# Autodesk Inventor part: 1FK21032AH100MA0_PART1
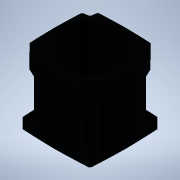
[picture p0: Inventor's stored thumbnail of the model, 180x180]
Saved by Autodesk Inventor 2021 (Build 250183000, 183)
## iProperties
Created: 2025-04
Part Number: 1FK21032AH100MA0_PART1
Material: Generic
Catalog Web Link: www.3dfindit.com
Description: -Servo synchronous motor
Document SubType Name: Modeling
Designer: psAdmin
Mass: 67.0011 g
Surface Area: 303.908 cm^2
Volume: 67.0011 cm^3
Density: 1 g/cm^3
Appearance: PSOLRGB-176-176-176
Category: PARTsolutions
Title: 1FK21032AH100MA0_PART1
Author: Cadenas PARTsolutions
Comments: Servo synchronous motor
Sending System: PARTsolutions
Preprocessor: ST-DEVELOPER v19.3
PSOL_IDENT_0: {$CADENAS_DATA/23d-libs/siemens_ag/_cat_/12/33/1fk21032ah100ma0.prj},213 {VTYP=3D},{NB=1FK21032AH100
PSOL_IDENT_1: MA0_PART1},{LINA=1FK21032AH100MA0_PART1},{NN=1FK21032AH100MA0_PART1},{NOPRJ=TRUE},{DATE=19.08.2025 1
PSOL_IDENT_2: 4:00:27},{GEOMDATE=30.07.2025 02:02:58},{VERSION=},{LINEID=10},{WBVAR=},{WBNUMERIC=}  {NB=1FK21032AH
PSOL_IDENT_3: 100MA0_PART1},{LINA=1FK21032AH100MA0_PART1},{KT=DUMMY},{PREVIEW=../../../_pool_/d3/78/p_d211_xx_0093
PSOL_IDENT_4: 4j.png},{DESCSHORT=SIMOTICS S-1FK2 HD, SINAMICS S210 3AC 400V-480V, 0.59 Nm, 4500 rpm},{DESCLONG=SIM
PSOL_IDENT_5: OTICS S-1FK2 HD servo motor M0=0.64 Nm; PN = 0.28 kW at nN=4500 rpm (380-480 V); PN = 0.167 kW at nN=
PSOL_IDENT_6: 2500 rpm (200-240 V); with holding brake; degree of protection IP64; cylindrical shaft D14 x 30 mm;
PSOL_IDENT_7: absolute encoder 22-bit + 12-bit multiturn (encoder AM22DQC); with OCC interface; plug size M17, rot
PSOL_IDENT_8: atable; SIMOTICS S-1FK2 servomotorfor a wide range of uses in industrial environments. SIMOTICS S‑1F
PSOL_IDENT_9: K2 servomotors are compact synchronous motors with a high dynamic performance that set themselves ap
PSOL_IDENT_10: art as a result of their high power density, degree of protection and overload capability. The motor
PSOL_IDENT_11: s are available in two variants: as High Dynamic variant (highest dynamic performance as a result of
PSOL_IDENT_12: the low intrinsic moment of inertia for applications demanding a high dynamic performance with low
PSOL_IDENT_13: moved masses) - and as Compact variant (precise and stable closed-loop control for medium up to larg
PSOL_IDENT_14: e moved masses as a result of a medium intrinsic moment of inertia). SIMOTICSS‑1FK2 servomotors full
PSOL_IDENT_15: y exploit their strengths in a system with the SINAMICSS210 frequency converter and simple connectio
PSOL_IDENT_16: n using the one cable connection (OCC). Advantages include the short control and positioning times,
PSOL_IDENT_17: fast and precise correction of disturbing quantities as well as stable control with a high dynamic p
PSOL_IDENT_18: erformance. The servo motors can be configured to address a wide range of requirements. For example
PSOL_IDENT_19: with and without holding brake, IP64 or IP65 degree of protection, singleturn or multiturn absolute
PSOL_IDENT_20: encoders - to name just a few. Further, the servomotors are available in different shaft heights ext
PSOL_IDENT_21: ending from 20 to 100. A shaft sealing ring is available to achieve an IP65 degree of protection and
PSOL_IDENT_22: for subsequent mounting at the motor or as spare part. SIMOTICS - the optimum motor for each and ev
PSOL_IDENT_23: ery motion control application.},{INTNO=195125315563},{SUPPLIERALTNO=1FK2103-2AH10-0MA0},{MANUID=1FK
PSOL_IDENT_24: 21032AH100MA0},{MANUNAME=Siemens},{MANUTYPEDESC=SYNCHRONOUS MOTOR 1FK2 HD 0,64 NM},{AAU732=SIMOTICS}
PSOL_IDENT_25: ,{AAO057=S-1FK2},{AAU734=SIMOTICS S-1FK2 HD servo motor M0=0.64 Nm; PN = 0.28 kW at nN=4500 rpm (380
PSOL_IDENT_26: -480 V); PN = 0.167 kW at nN=2500 rpm (200-240 V); with holding brake; degree of protection IP64; cy
PSOL_IDENT_27: lindrical shaft D14 x 30 mm; absolute encoder 22-bit + 12-bit multiturn (encoder AM22DQC); with OCC
PSOL_IDENT_28: interface; plug size M17, rotatable;},{AAW338=SYNCHRONOUS MOTOR 1FK2 HD 0,64 NM},{AAO742=SIMOTICS},{
PSOL_IDENT_29: AAO663=4034106444723},{NOCUPEROU=1},{PRICEQUANTITY=1},{QUANTITYMIN=1},{QUANTITYINT=1},{CTN=85015100}
PSOL_IDENT_30: ,{COO=RO},{AAO676=1FK2103-2AH10-0MA0},{AAO677=Siemens AG},{ORDERUNIT=C62},{CONTENTUNIT=C62}
NB: 1FK21032AH100MA0_PART1
NT: Servo synchronous motor
NBSYN: $MANUID._PART1
LINA: 1FK21032AH100MA0_PART1
CATALOG: SIEMENS
PREVIEW: ../../../_pool_/d3/78/p_d211_xx_00934j.png
DESCSHORT: SIMOTICS S-1FK2 HD, SINAMICS S210 3AC 400V-480V, 0.59 Nm, 4500 rpm
DESCLONG: SIMOTICS S-1FK2 HD servo motor M0=0.64 Nm; PN = 0.28 kW at nN=4500 rpm (380-480 V); PN = 0.167 kW at nN=2500 rpm (200-240 V); with holding brake; degree of prot
INTNO: 195125315563
SUPPLIERALTNO: 1FK2103-2AH10-0MA0
MANUID: 1FK21032AH100MA0
MANUNAME: Siemens
MANUTYPEDESC: SYNCHRONOUS MOTOR 1FK2 HD 0,64 NM
AAU732: SIMOTICS
AAO057: S-1FK2
AAU734: SIMOTICS S-1FK2 HD servo motor M0=0.64 Nm; PN = 0.28 kW at nN=4500 rpm (380-480 V); PN = 0.167 kW at nN=2500 rpm (200-240 V); with holding brake; degree of prot
AAW338: SYNCHRONOUS MOTOR 1FK2 HD 0,64 NM
AAO742: SIMOTICS
AAO663: 4034106444723.0
NOCUPEROU: 1
PRICEQUANTITY: 1
QUANTITYMIN: 1
QUANTITYINT: 1
CTN: 85015100
COO: RO
ARTICLENO: 1FK21032AH100MA0_PART1
BOMINFO: 1FK21032AH100MA0_PART1
CREATOR: CADENAS GmbH
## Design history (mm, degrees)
feature "2025_04_17_15_06_16_0549"
node "ECLASS_CAX_IMPORTER_001_CP_0_XY"
node "ECLASS_CAX_IMPORTER_001_CP_0_YZ"
node "ECLASS_CAX_IMPORTER_001_CP_0_ZX"
node "ECLASS_CAX_IMPORTER_001_CP_0_X"
node "ECLASS_CAX_IMPORTER_001_CP_0_Y"
node "ECLASS_CAX_IMPORTER_001_CP_0_Z"
node "ECLASS_CAX_IMPORTER_001_CP_0_Center"
node "ECLASS_CAX_IMPORTER_001_CP_1_XY"
node "ECLASS_CAX_IMPORTER_001_CP_1_YZ"
node "ECLASS_CAX_IMPORTER_001_CP_1_ZX"
node "ECLASS_CAX_IMPORTER_001_CP_1_X"
node "ECLASS_CAX_IMPORTER_001_CP_1_Y"
node "ECLASS_CAX_IMPORTER_001_CP_1_Z"
node "ECLASS_CAX_IMPORTER_001_CP_1_Center"
body "Solid1"
